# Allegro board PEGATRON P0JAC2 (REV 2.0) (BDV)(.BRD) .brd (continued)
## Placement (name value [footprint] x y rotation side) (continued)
R7160  -  [TX_R0402]  71.4 24.42 0 bottom
R7161  -  [TX_R0402]  69.8 24.63 180 bottom
R7166  -  [TX_R0402]  58.64 13.01 180 bottom
R7171  -  [TX_R0402]  60.42 14.55 0 bottom
R7177  -  [TX_R0402]  65.17 14.66 180 bottom
R7178  -  [TX_R0402]  61.95 12.63 0 bottom
R7181  -  [TX_R0402]  64.62 24.52 180 bottom
R7182  -  [TX_R0402]  64.24 25.71 270 bottom
R7183  -  [R0603]  63.22 24.72 90 bottom
R7184  -  [TX_R0402]  65.18 13.14 0 bottom
R7185  -  [TX_R0402]  61.77 13.88 90 bottom
R7186  -  [TX_R0402]  85.19 14.11 270 bottom
R7189  -  [TX_R0402]  85.95 14.11 270 bottom
R7190  -  [TX_R0402]  61.77 15.43 90 bottom
R7194  -  [TX_R0402]  65.75 23.75 270 bottom
R7195  -  [TX_R0402]  59.97 16.44 270 bottom
R7199  -  [TX_R0402]  66.47 22.15 270 bottom
R7355  -  [TX_R0402]  46.53 12.63 0 bottom
R7356  -  [TX_R0402]  46.53 13.37 0 bottom
R7357  -  [TX_R0402]  48.05 13.37 0 bottom
R7358  -  [TX_R0402]  44.98 13.37 0 bottom
R7359  -  [TX_R0402]  43.28 14.46 180 bottom
R7360  -  [TX_R0402]  48.06 12.63 180 bottom
R7370  -  [TX_R0402]  80.01 9.11 270 bottom
R7371  -  [TX_R0402]  80.75 9.11 270 bottom
R7373  -  [TX_R0402]  82.55 5.83 180 bottom
R7374  -  [TX_R0402]  78.26 9.11 270 bottom
R8100  -  [TX_R0402]  73.94 45.73 180 bottom
R8101  -  [TX_R0402]  73.94 41.54 90 bottom
R8103  -  [TX_R0402]  73.83 44.61 90 bottom
R8111  -  [TX_R0402]  74.68 41.54 270 bottom
R8112  -  [TX_R0402]  73.1 44.61 270 bottom
R8113  -  [TX_R0402]  72.08 41.45 180 bottom
R8114  -  [TX_R0402]  73.2 41.54 90 bottom
R8116  -  [TX_R0603_0OHM_H24]  35.58 40.19 180 bottom
R8117  -  [TX_R0402]  35.36 41.51 90 bottom
R8118  -  [TX_R0402]  43.31 48.35 270 bottom
R8119  -  [TX_R0402]  43.31 49.9 90 bottom
R8120  -  [TX_R0402]  35.43 43.42 0 bottom
R8121  -  [TX_R0402_0OHM]  30.73 42.38 270 bottom
R8122  -  [TX_R0603_0OHM_H24]  36.54 44.54 0 bottom
R8123  -  [TX_R0402]  34.62 41.51 270 bottom
R8124  -  [TX_R0402]  80.04 83.46 0 bottom
R8125  -  [TX_R0402]  74.46 82.29 270 bottom
R8126  -  [TX_R0402]  73.73 82.29 90 bottom
R8127  -  [TX_R0402]  79.63 82.31 270 bottom
R8128  -  [TX_R0402]  73.73 84.67 90 bottom
R8129  -  [TX_R0402]  39.9 47.99 0 bottom
R8130  -  [TX_R0402]  39.9 48.75 0 bottom
R8131  -  [TX_R0402]  40.26 49.92 90 bottom
R8132  -  [TX_R0402]  36.12 41.51 270 bottom
R8133  -  [TX_R0402]  36.96 43.01 0 bottom
R8203  -  [TX_R1206_H30]  67.18 50.25 90 bottom
R8205  -  [TX_R1206_H30]  59.38 51.9 0 bottom
R8208  -  [TX_R0603_H24]  73.78 28.58 180 bottom
R8209  -  [TX_R0402]  71.07 32.14 180 bottom
R8210  -  [TX_R0402]  54.08 52 90 bottom
R8211  -  [TX_R0402]  68.81 52.08 270 bottom
R8212  -  [TX_R0402]  51.43 22.97 180 bottom
R8213  -  [TX_R0603_H24]  46.27 37.3 90 bottom
R8214  -  [TX_R0402]  69.57 52.08 270 bottom
R8216  -  [TX_R0603_H24]  45.41 29.8 270 bottom
R8218  -  [TX_R0603_0OHM_H24]  59.82 22.06 0 bottom
R8224  -  [TX_R0402]  54.91 21.26 90 bottom
R8227  -  [TX_R0603_H24]  50.03 15.07 180 bottom
R8250  -  [TX_R0402]  50.03 19.26 0 bottom
R8301  -  [TX_R0402]  45.97 32.34 270 bottom
R8302  -  [TX_R0402]  72.82 25.54 270 bottom
R8305  -  [TX_R0402]  44.47 43.04 90 bottom
R8306  -  [TX_R0402]  44.82 38.78 180 bottom
R8307  -  [TX_R0402]  44.82 39.51 180 bottom
R8308  -  [TX_R0402]  42.88 45.98 90 bottom
R8309  -  [TX_R0402]  43.63 39.07 90 bottom
R8310  -  [TX_R0603_H24]  56.01 22.72 90 bottom
R8312  -  [TX_R0402]  58.31 18.04 270 bottom
R8313  -  [TX_R0402]  73.91 24.9 270 bottom
R8314  -  [TX_R0402]  75.9 24.47 0 bottom
R8315  -  [TX_R0402]  80.04 27.16 90 bottom
R8316  -  [TX_R0402]  80.41 26.02 0 bottom
R8317  -  [TX_R0402]  35.68 59.9 0 bottom
R8318  -  [TX_R0402]  35.81 65.47 90 bottom
R8320  -  [TX_R0603_H24]  70.74 40.78 90 bottom
R8323  -  [TX_R0402_H22]  87.81 108.52 270 bottom
R8324  -  [TX_R0402_H22]  39.29 2.8 0 bottom
R8325  -  [TX_R0402]  73.74 30.92 270 bottom
R8326  -  [TX_R0402]  76.84 30.95 270 bottom
R8327  -  [TX_R0402_H22]  51.68 59.56 0 bottom
R8328  -  [TX_R0402]  75.31 30.95 270 bottom
R8329  -  [TX_R0402]  76.07 30.95 270 bottom
R8330  -  [TX_R0402]  72.93 34.09 270 bottom
R8335  -  [TX_R0402]  57.56 19.57 270 bottom
R8337  -  [TX_R0402]  45.87 53.12 180 bottom
R8340  -  [TX_R0402]  72.92 32.55 90 bottom
R8365  -  [TX_R0402]  71.75 28.01 180 bottom
R8366  -  [TX_R0201_0OHM_H10]  43.05 40.55 270 bottom
R8367  -  [TX_R0402]  57.56 18.02 90 bottom
R8368  -  [TX_R0402]  56.84 19.57 90 bottom
R8369  -  [TX_R0402]  80.44 22.62 180 bottom
R8370  -  [TX_R0402]  78.87 23.25 0 bottom
R8372  -  [TX_R0402]  75.65 29.78 180 bottom
R8373  -  [TX_R0402_H22]  40.37 28.22 270 bottom
R8375  -  [TX_R0402]  46.3 43.98 90 bottom
R8376  -  [TX_R0402]  47.07 43.98 90 bottom
R8377  -  [TX_R0402]  64.01 21.52 270 bottom
R8379  -  [TX_R0402]  80.09 23.73 270 bottom
R8401  -  [TX_R0201_0OHM_H10]  58.67 20.94 270 bottom
R8404  -  [TX_R0402]  37.87 41.89 90 bottom
R8405  -  [TX_R0402]  42.46 42 90 bottom
R8406  -  [TX_R0402]  39.5 49.92 270 bottom
R8417  -  [TX_R0402]  59.82 19.57 90 bottom
R8430  -  [TX_R0402]  35.68 52.31 90 bottom
R8431  -  [TX_R0402]  69.82 26.63 180 bottom
R8435  -  [TX_R0402]  69.82 25.89 180 bottom
R8437  -  [TX_R0402]  31.09 50.71 270 bottom
R8438  -  [TX_R0402]  36.57 52.16 90 bottom
R8448  -  [TX_R0201_0OHM_H10]  59.21 20.94 90 bottom
R8449  -  [TX_R0402]  73.68 27.24 270 bottom
R8450  -  [TX_R0402]  72.04 35.85 270 bottom
R8456  -  [TX_R0402]  74.85 33.72 0 bottom
R8457  -  [TX_R0402]  72.82 35.86 270 bottom
R8458  -  [TX_R0402]  74.85 34.48 0 bottom
R8501  -  [TX_R0402]  45.13 51.72 0 bottom
R8502  -  [TX_R0402]  46.68 50.99 0 bottom
R8503  -  [TX_R0402]  46.68 50.25 0 bottom
R8504  -  [TX_R0402]  46.68 51.72 0 bottom
R8505  -  [TX_R0402]  45.13 50.99 0 bottom
R8506  -  [TX_R0402]  45.13 50.25 0 bottom
R8507  -  [TX_R0402]  49.35 25.23 0 bottom
R8508  -  [TX_R0402]  49.35 24.49 180 bottom
R8509  -  [TX_R0402]  69.72 27.39 180 bottom
R8510  -  [TX_R0402]  69.72 28.13 0 bottom
R8511  -  [TX_R0402]  69.55 32.14 0 bottom
R8515  -  [TX_R0402]  47.07 45.55 90 bottom
R8517  -  [TX_R0402]  46.3 45.55 270 bottom
R8526  -  [TX_R0402]  45.03 47.94 0 bottom
R8527  -  [TX_R0402]  45.03 49.41 0 bottom
R8528  -  [TX_R0201_H10]  71.43 37.98 180 bottom
R8529  -  [TX_R0201_H10]  71.43 37.46 180 bottom
R8530  -  [TX_R0402]  45.03 48.68 0 bottom
R8531  -  [TX_R0201_0OHM_H10]  71.43 36.89 180 bottom
R8800  -  [TX_R0603_H24]  37.74 24.16 0 bottom
R8801  -  [TX_R0805_H26]  67.11 8.47 270 bottom
R8803  -  [TX_R0402]  34.39 18.04 90 bottom
R8804  -  [TX_R0402]  29.2 26.6 90 bottom
R8805  -  [TX_R0402]  34.64 20.38 270 bottom
R8806  -  [TX_R0402]  30.7 20.37 270 bottom
R8807  -  [TX_R0402_0OHM]  30.51 24.7 180 bottom
R8808  -  [TX_R0402_0OHM]  29.58 23.07 0 bottom
R8809  -  [TX_R0402]  29.58 22.34 180 bottom
R8810  -  [TX_R0402]  30.7 23.43 270 bottom
R8811  -  [TX_R0402]  33.73 20.41 270 bottom
R8812  -  [TX_R0402]  39.24 26.22 0 bottom
R8813  -  [TX_R0402_H22]  39.24 26.96 0 bottom
R8814  -  [TX_R0402]  39.31 24.98 90 bottom
R8820  -  [TX_R0402]  32.43 15.66 90 bottom
R8821  -  [TX_R0402]  33.43 16.93 0 bottom
R8822  -  [TX_R0402]  29.2 25.05 90 bottom
R8825  -  [TX_R0402]  29.85 18.7 90 bottom
R8826  -  [TX_R0402]  31.45 18.35 270 bottom
R8833  -  [TX_R0402_0OHM]  31.43 20.39 90 bottom
R8834  -  [TX_R0402]  29.97 20.49 90 bottom
R8835  -  [TX_R0402]  29.58 23.83 0 bottom
R8874  -  [TX_R0402]  32.18 20.39 90 bottom
R8875  -  [TX_R0402]  32.89 18.35 90 bottom
R8876  -  [TX_R0402]  32.18 18.35 90 bottom
R8878  -  [TX_R0402]  32.89 20.38 90 bottom
R8903  -  [TX_R0402]  30.02 33.94 180 bottom
R8904  -  [TX_R0402]  30.03 36.18 0 bottom
R8905  -  [TX_R0402]  32.15 37.7 90 bottom
R8906  -  [TX_R0402]  34.82 38.19 0 bottom
R8907  -  [TX_R0402]  34.44 33.93 90 bottom
R8908  -  [TX_R0805_H24]  29.21 48.07 90 bottom
R8910  -  [TX_R0402]  29.24 46.16 180 bottom
R8923  -  [TX_R0402]  29.93 37.7 270 bottom
R8944  -  [TX_R0402]  30.02 34.68 0 bottom
R8971  -  [TX_R0402]  29.2 37.7 270 bottom
R8972  -  [TX_R0402]  30.66 37.7 270 bottom
R8973  -  [TX_R0402]  31.41 37.7 270 bottom
R8974  -  [TX_R0402]  29.31 44.76 180 bottom
R9000  -  [TX_R0402]  41.17 22.26 180 bottom
R9001  -  [TX_R0402]  47.11 22.31 180 bottom
R9002  -  [TX_R0402]  47.11 23.05 0 bottom
R9003  -  [TX_R0402]  41.17 26.68 180 bottom
R9004  -  [TX_R0402_0OHM]  41.17 21.52 0 bottom
R9005  -  [TX_R0402]  41.17 23 0 bottom
R9006  -  [TX_R0805_H26]  47.14 20.53 270 bottom
RN0900  -  [TX_2R4P0402_H18]  87.92 44.46 90 bottom
RN0901  -  [TX_2R4P0402_H18]  87.92 47.51 90 bottom
RN0902  -  [TX_2R4P0402_H18]  87.92 41.31 90 bottom
RN0903  -  [TX_2R4P0402_H18]  87.92 38.21 90 bottom
RN2104  -  [TX_2R4P0402_H18]  21.36 98.36 180 bottom
RN2105  -  [TX_2R4P0402_H18]  22.57 98.36 180 bottom
RN7309  -  [TX_2R4P0402_H18]  64.56 6.56 270 bottom
RN7337  -  [TX_2R4P0402_H18]  64.56 7.96 270 bottom
RN7338  -  [TX_2R4P0402_H18]  64.56 5.22 270 bottom
RN7340  -  [TX_2R4P0402_H18]  64.59 2.45 270 bottom
RN7341  -  [TX_2R4P0402_H18]  64.56 3.82 270 bottom
RNX5227  -  [TX_2R4P0402_H18]  87.88 58.25 90 bottom
SP2601  -  [NB_R0402_SHORT_5MIL_SMALL]  64.11 61.8 90 bottom
SP2602  -  [NB_R0402_SHORT_5MIL_SMALL]  43.42 59.57 0 bottom
SP2603  -  [NB_R0402_SHORT_5MIL_SMALL]  38.38 100.97 270 bottom
SP7301  -  [HH_R0402_SHORT_12MIL]  82.25 9.06 0 bottom
SP7302  -  [HH_R0402_SHORT_12MIL]  77.06 6.84 180 bottom
SP7303  -  [HH_R0402_SHORT_12MIL]  79.12 5.04 180 bottom
SP7304  -  [HH_R0402_SHORT_12MIL]  77.06 6 0 bottom
SP7305  -  [HH_R0402_SHORT_12MIL]  79.15 4.2 0 bottom
SP7306  -  [HH_R0402_SHORT_12MIL]  81.1 4.76 180 bottom
SP7307  -  [HH_R0402_SHORT_12MIL]  86.03 8.98 180 bottom
SP7308  -  [HH_R0402_SHORT_12MIL]  86.72 5.04 0 bottom
SR8100  -  [NB_PWR_FB_SHORT_PT]  34.92 44.99 90 bottom
SR8501  -  [NB_R0402_SHORT_5MIL_SMALL]  55.96 20.66 270 bottom
SR8900  -  [NB_R0402_SHORT]  36.42 37.93 90 bottom
SR9000  -  [NB_R0402_SHORT]  47.36 24.98 0 bottom
SR9001  -  [NB_R0402_SHORT]  47.36 23.94 0 bottom
SR9002  -  [NB_R0402_SHORT]  47.36 26.02 0 bottom
SR9003  -  [NB_R0402_SHORT]  43.96 27.95 90 bottom
SW2004  -  [TX_SW_3P_45_2HOLD]  100.5 95.6 270 bottom
T1101  -  [NB_TPC26T_68]  10.09 65.99 180 bottom
T1102  -  [NB_TPC26T_68]  16.16 66.14 180 bottom
T1103  -  [NB_TPC26T_68]  32.11 65.3 180 bottom
T1104  -  [NB_TPC26T_68]  34.57 7.03 180 bottom
T1105  -  [NB_TPC26T_68]  30.23 61.74 180 bottom
T1106  -  [NB_TPC26T_68]  31.4 63.09 180 bottom
T1610  -  [NB_TPC26T_68]  69.55 81.16 180 bottom
T1611  -  [NB_TPC26T_68]  85.14 45.98 180 bottom
T1901  -  [NB_TPC22T_68]  31.79 69.1 0 bottom
T1902  -  [NB_TPC22T_68]  27.97 75.47 0 bottom
T1903  -  [NB_TPC22T_68]  32.51 71.89 270 bottom
T1904  -  [NB_TPC22T_68]  21.84 86.57 0 top
T1905  -  [NB_TPC22T_68]  21.74 92.44 0 top
T2005  -  [NB_TPC26T_68]  94.49 93.53 180 bottom
T2006  -  [NB_TPC26T_68]  88.27 39.63 180 bottom
T2007  -  [NB_TPC26T_68]  13.7 66.01 180 bottom
T2008  -  [NB_TPC26T_68]  11.88 65.96 180 bottom
T2009  -  [NB_TPC26T_68]  8.97 75.98 180 bottom
T2010  -  [NB_TPC26T_68]  40.92 7.16 180 bottom
T2011  -  [NB_TPC26T_68]  8.35 66.12 180 bottom
T2012  -  [NB_TPC26T_68]  8.38 63.46 180 bottom
T2013  -  [NB_TPC26T_68]  88.19 45.96 180 bottom
T2101  -  [NB_TPC22T_68]  11.14 120.61 180 bottom
T2102  -  [NB_TPC22T_68]  1.96 120.33 180 bottom
T2103  -  [NB_TPC22T_68]  12.07 122.08 180 bottom
T2104  -  [NB_TPC22T_68]  1.96 122.06 180 bottom
T2301  -  [NB_TPC26T_68]  79.48 3.25 180 bottom
T2302  -  [NB_TPC26T_68]  29.71 78.56 180 bottom
T2508  -  [NB_TPC22T_68]  59.11 71.46 0 top
T2509  -  [NB_TPC22T_68]  62.38 70.9 0 top
T2541  -  [NB_TPC22T_68]  58.04 72.91 0 top
T2542  -  [NB_TPC22T_68]  72.9 74.46 180 bottom
T2600  -  [NB_TPC22T_68]  39.42 63.89 270 bottom
T2601  -  [NB_TPC22T_68]  40.3 62.39 270 bottom
T2602  -  [NB_TPC22T_68]  38.47 62.39 270 bottom
T2608  -  [NB_TPC22T_68]  61.7 67.5 270 top
T2618  -  [NB_TPC22T_68]  61.62 65.72 0 top
T2623  -  [NB_TPC22T_68]  47.63 62.9 0 top
T2624  -  [NB_TPC22T_68]  88.77 90.56 180 bottom
T2625  -  [NB_TPC22T_68]  84.91 70.63 180 bottom
T2646  -  [NB_TPC22T_68]  45.52 68.41 0 top
T2657  -  [NB_TPC22T_68]  48.05 73.03 0 top
T2670  -  [NB_TPC22T_68]  63.25 68.31 0 top
T2685  -  [NB_TPC22T_68]  61.24 69.28 0 top
T2686  -  [NB_TPC22T_68]  40.18 65.44 180 bottom
T2700  -  [NB_TPC22T_68]  56.26 74.41 270 top
T2701  -  [NB_TPC22T_68]  50.8 74.41 0 top
T2702  -  [NB_TPC22T_68]  53.06 73.47 0 top
T2703  -  [NB_TPC22T_68]  55.63 66.33 270 top
T2704  -  [NB_TPC22T_68]  54.79 73.34 0 top
T2705  -  [NB_TPC22T_68]  61.42 72.6 0 top
T2706  -  [NB_TPC26T_68]  79.29 67.26 180 bottom
T2707  -  [NB_TPC26T_68]  90.63 93.86 180 bottom
T3002  -  [NB_TPC26T_68]  71.18 70.1 270 top
T3003  -  [NB_TPC26T_68]  70.04 71.67 270 top
T3005  -  [NB_TPC26T_68]  25.05 98.56 180 bottom
T3006  -  [NB_TPC26T_68]  25.5 100.26 180 bottom
T3007  -  [NB_TPC26T_68]  84.99 84.9 180 bottom
T3008  -  [NB_TPC26T_68]  21.97 106.77 180 bottom
T3010  -  [NB_TPC22T_68]  68.45 68.44 0 top
T3101  -  [NB_TPC22T_68]  53.29 107.58 180 bottom
T3801  -  [NB_TPC22T_68]  87.58 103.46 180 bottom
T3802  -  [NB_TPC22T_68]  87.43 101.43 180 bottom
T3803  -  [NB_TPC22T_68]  89.18 85.3 180 bottom
T3804  -  [NB_TPC22T_68]  88.88 87.03 180 bottom
T5401  -  [NB_TPC22T_68]  16.4 76.59 180 bottom
T5402  -  [NB_TPC22T_68]  10.44 69.6 180 bottom
T5403  -  [NB_TPC22T_68]  20.96 77.05 0 top
T5404  -  [NB_TPC22T_68]  14.22 69.6 180 bottom
T5405  -  [NB_TPC22T_68]  6.06 71.28 180 bottom
T5406  -  [NB_TPC22T_68]  84.96 103.92 180 bottom
T5407  -  [NB_TPC22T_68]  6.53 72.95 180 bottom
T5807  -  [NB_TPC22T_68]  27.38 99.81 180 bottom
T8001  -  [NB_TPC26T_68]  73.23 7.78 0 bottom
T8002  -  [NB_TPC26T_68]  71.44 7.72 0 bottom
T8004  -  [NB_TPC26T_68]  87.12 26.1 0 bottom
T8005  -  [NB_TPC26T_68]  85.28 11.13 0 bottom
T8006  -  [NB_TPC26T_68]  75.7 7.78 0 bottom
T8100  -  [NB_TPC28T_68]  75.74 44.99 270 top
T8101  -  [NB_TPC22T_68]  34.8 39.1 180 bottom
T8102  -  [NB_TPC22T_68]  34.34 44.15 0 top
T8103  -  [NB_TPC22T_68]  32.6 44.09 0 top
T8104  -  [NB_TPC22T_68]  38.13 44.24 180 bottom
T8105  -  [NB_TPC22T_68]  74.02 86.01 180 bottom
T8106  -  [NB_TPC22T_68]  85.04 80.91 180 bottom
T8107  -  [NB_TPC22T_68]  34.44 109.69 180 bottom
T8201  -  [NB_TPC22T_68]  37 33.48 180 bottom
T8202  -  [NB_TPC22T_68]  75.43 28.65 180 bottom
T8203  -  [NB_TPC22T_68]  78.61 30.06 180 bottom
T8204  -  [NB_TPC22T_68]  48.4 22.44 180 bottom
T8205  -  [NB_TPC22T_68]  41.54 13.91 180 bottom
T8206  -  [NB_TPC22T_68]  46.13 38.88 180 bottom
T8207  -  [NB_TPC22T_68]  69.69 106.08 180 bottom
T8304  -  [NB_TPC26T_68]  58.62 17.26 270 top
T8305  -  [NB_TPC22T_68]  43.33 32.44 180 bottom
T8306  -  [NB_TPC22T_68]  42.09 43.72 270 bottom
T8307  -  [NB_TPC22T_68]  14.68 106.33 270 bottom
T8308  -  [NB_TPC22T_68]  22.86 71.4 270 bottom
T8309  -  [NB_TPC22T_68]  41.82 46.09 270 bottom
T8310  -  [NB_TPC22T_68]  42.7 39.46 270 bottom
T8311  -  [NB_TPC22T_68]  93.92 85.79 270 bottom
T8312  -  [NB_TPC22T_68]  27.97 78.69 270 bottom
T8313  -  [NB_TPC22T_68]  86.52 36.95 270 bottom
T8314  -  [NB_TPC22T_68]  26.19 78.62 180 bottom
T8315  -  [NB_TPC22T_68]  38.94 106.46 180 bottom
T8316  -  [NB_TPC22T_68]  61.74 106.06 180 bottom
T8317  -  [NB_TPC22T_68]  45.73 106.35 180 bottom
T8318  -  [NB_TPC26T_68]  36.96 35.76 180 bottom
T8319  -  [NB_TPC26T_68]  49.18 110.3 180 bottom
T8320  -  [NB_TPC22T_68]  41.07 32.99 270 bottom
T8321  -  [NB_TPC22T_68]  55.38 29.09 270 top
T8322  -  [NB_TPC22T_68]  45.42 42.99 180 bottom
T8323  -  [NB_TPC22T_68]  48.11 42.2 180 bottom
T8403  -  [NB_TPC22T_68]  55.96 41.16 270 top
T8405  -  [NB_TPC22T_68]  53.49 38.39 270 top
T8406  -  [NB_TPC22T_68]  51.87 39.53 270 top
T8407  -  [NB_TPC22T_68]  54.36 40.4 270 top
T8410  -  [NB_TPC22T_68]  54.03 36.43 270 top
T8411  -  [NB_TPC22T_68]  52.71 35.26 270 top
T8415  -  [NB_TPC22T_68]  60.56 20.86 270 bottom
T8416  -  [NB_TPC22T_68]  57.86 30.9 270 top
T8417  -  [NB_TPC22T_68]  62.71 7.71 180 bottom
T8418  -  [NB_TPC22T_68]  77.17 108.54 180 bottom
T8419  -  [NB_TPC22T_68]  38.28 46.34 180 bottom
T8420  -  [NB_TPC22T_68]  86.84 84.08 180 bottom
T8425  -  [NB_TPC22T_68]  55.96 25.74 270 top
T8426  -  [NB_TPC22T_68]  58.85 29.47 0 top
T8428  -  [NB_TPC22T_68]  59.97 39.18 0 top
T8430  -  [NB_TPC22T_68]  63.35 41.06 180 bottom
T8431  -  [NB_TPC22T_68]  62.64 35.72 0 top
T8464  -  [NB_TPC22T_68]  52.76 41.06 0 top
T8501  -  [NB_TPC22T_68]  70.31 38.72 90 top
T8502  -  [NB_TPC22T_68]  70.77 37.02 90 top
T8503  -  [NB_TPC22T_68]  46.41 47.58 90 bottom
T8504  -  [NB_TPC22T_68]  46.36 49.35 90 bottom
T8505  -  [NB_TPC22T_68]  43.79 47.05 90 bottom
T8506  -  [NB_TPC22T_68]  79.27 61.63 180 bottom
T8507  -  [NB_TPC22T_68]  77.39 61.48 180 bottom
T8800  -  [NB_TPC22T_68]  37.31 16.67 0 bottom
T8801  -  [NB_TPC26T_68]  66.23 6.47 180 bottom
T8802  -  [NB_TPC26T_68]  85.37 39.74 180 bottom
T8902  -  [NB_TPC28T_68]  33.36 35.65 0 top
T8903  -  [NB_TPC28T_68]  30.02 34.93 0 top
T8904  -  [NB_TPC28T_68]  32.84 32.6 180 bottom
T8905  -  [NB_TPC28T_68]  8.5 68.11 180 bottom
T8906  -  [NB_TPC28T_68]  29.85 37.27 0 top
T8907  -  [NB_TPC28T_68]  31.6 37.22 0 top
U1001  -  [TX_QFN_48P_16_S236_P_RE_10V]  27.55 65.74 180 bottom
U1101  -  [TX_MICROPHONE_6P_148X186_KN]  98.14 111.96 270 top
U1601  -  [TX_BGA_253P_20_492X492]  65.36 93.98 270 bottom
U1701  -  [TX_BGA_253P_20_492X492]  47.58 93.98 270 bottom
U1915  -  [TX_BGA_169P_20_630X472_H39]  30.98 90.48 180 bottom
U2101  -  [TX_SOT23_S5_H57]  77.86 96.99 180 bottom
U2301  -  [TX_SOT23_S5_H57]  86.31 2.8 0 bottom
U2400  -  [T_HH_BGA_1380P_669X669]  53.42 71.02 270 bottom
U3001  -  [TX_QFP_64P_16_354X354_H63]  72.76 68.54 0 bottom
U3301  -  [TX_BGA_24P_20_118X118]  77.04 87.74 270 bottom
U3302  -  [TX_DFN_8P_50_197X236_PAD_WI]  76.71 92.69 90 bottom
U3304  -  [TX_DFN_8P_18_79X79]  78.46 78.57 180 bottom
U5101  -  [TX_QFN_10P_20_79X61]  29.29 8.32 270 bottom
U5203  -  [TX_SOIC_8P_26_122X193]  73.76 51.44 90 bottom
U5401  -  [TX_LGA_96P_20_12PAD_FOXCO]  9.6 85.04 270 bottom
U5801  -  [TX_QFN_24P_16_S118_P_INVH37]  31.78 99.37 180 bottom
U5803  -  [TX_OPLGA_6P_24_71X93_CAPELL]  92.96 117.46 90 top
U5804  -  [TX_BGA_8P_16_47X47]  68.22 117.16 180 bottom
U5806  -  [TX_SOT23_2D4_H57]  94.7 79.9 0 top
U7107  -  [TX_QFN_48P_20_S276_P_QL_16V]  69.72 17.61 0 bottom
U7112  -  [TX_SO8_H69]  13.67 61.66 270 bottom
U7141  -  [TX_SOT23_S5_H57]  54.25 17.18 0 bottom
U7311  -  [TX_SOT23_S5_H57]  46.16 15.39 0 bottom
U7320  -  [TX_BGA_6P_20_55X35]  82.63 7.4 180 bottom
U7321  -  [TX_BGA_8P_20_75X35]  79.5 7.35 180 bottom
U7322  -  [TX_BGA_6P_20_55X35]  86.49 7.35 180 bottom
U7903  -  [NB_SHIELDING_52P_2HOLD]  54.71 32.85 0 bottom
U7911  -  [SMD79X157_NP]  17.76 9.9 180 bottom
U7913  -  [SMD79X157_NP]  45.73 1.01 270 bottom
U7920  -  [SMDPAD_394X394_NP]  34.92 6.31 0 top
U7921  -  [SMDPAD_394X394_NP]  14.1 100.24 0 top
U7922  -  [SMDPAD_394X394_NP]  28.06 55.08 0 top
U7931  -  [SMDPAD79X315_NP]  17.75 9.9 0 top
U7932  -  [SMDPAD79X315_NP]  45.7 1 90 top
U7942  -  [NB_SHIELD_58P_2H_2508X1831]  58.44 86.54 0 bottom
U8100  -  [TX_QFN_16P_26_S157_PD_TI_4V]  77.52 43.04 270 bottom
U8101  -  [TX_BGA_12P_16_66X51]  32.56 43.01 0 bottom
U8102  -  [TX_SOT23_S5_H57]  77.06 83.25 0 bottom
U8201  -  [TX_BGA_224P_16_244X244]  58.72 34.94 0 bottom
U8800  -  [TX_QFN_24P_20_S157_P_QU_4V]  33.97 23.43 180 bottom
U8901  -  [T_CSP_15P_20_103X77]  32.39 34.58 270 bottom
U9000  -  [TX_QFN_16P_20_S118_P_KT_5V]  44.22 24.42 90 bottom
X2600  -  [TX_XTAL_4P_126X98_EPSON]  39.98 60.39 180 bottom
X2601  -  [TX_XTAL_2P_126X59]  65.37 60 180 bottom

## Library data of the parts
C0706 C0710 C0715 C1902 C1905 C1909 C2011 C2608 C2611 C2612 C3317-C3319 C3801 C5402 C5405 C5878 C7104 C7105 = DEV_12
C0707 C0708 C0713 C0901 C1022 C1024 C1025 C1052 C1105 C1601-C1609 C1614 C1616 C1618 C1619 C1622 C1625 C1701 C1703 C1705 C1707 C1709-C1717 C1722 C1725 C1900 C1903 C1904 C1912-C1916 C2102 C2104 C2124 C2125 C2602 C2603 C2706 C2707 C2709 C2710 C2713 C2717 C2722-C2724 C2728-C2730 C2733 C2735-C2737 C2747 C2748 C2752-C2754 C2758-C2763 C2766-C2768 C2771 C2774 C2776 C2777 C2800 C2802-C2804 C2806-C2811 C2814 C2815 C2817-C2825 C3001 C5102 C5103 C5412 C5414 C5415 C7001 C7002 C7010 C7106 C7110 C7117 C7118 C7120 C7351 C7355-C7357 C7359 C8402 = DEV_10
C0714 C0787 C0951 C0952 C1911 C2122 C2600 C2601 C5217 C5403 C5413 C5416 C5841 C5866 C5867 C7166 C7187 C7341 C7342 C7350 C7353 C7364 C8299 C8367 = DEV_9
C0722 = DEV_28
C0902 C0903 C0904 C0905 C0906 C0907 C0908 C0909 C0910 C1002 C1020 C1021 C1023 C1026 C1027 C1029 C1053 C1615 C1617 C1623 C1624 C1702 C1704 C1723 C1724 C2036 C2101 C2126 C2401 C2604 C2732 C2772 C2773 C3101 C3311 C3316 C5101 C5209 C5215 C5216 C5404 C5407 C5410 C5411 C5417 C5810-C5813 C5819 C5820 C7003 C7011 C7146-C7149 C7352 C7354 C7377 C8003-C8005 = DEV_29
C1001 C1007 C1008 C1028 C1030 C1040 C1106 C7385 = DEV_65
C1003-C1006 C2718 C2727 C7119 C7317 C7318 C7358 = DEV_24
C1010 C1044-C1047 C1060-C1063 C2605 C7312 C7313 = DEV_27
C1102 = DEV_25
C2127 C2128 C8107 = DEV_157: room: 5V
C2301 = DEV_151
C2606 = DEV_164
C2610 = DEV_156
C2701 C7316 = DEV_58
C2734 C2816 C5211 C5212 C5401 C5406 C7103 = DEV_11
C3002 = DEV_68
C3003-C3011 = DEV_155
C5210 C5214 = DEV_154
C7108 C7109 C7111 C7112 C7330 C7331 C7388-C7391 = DEV_153
C7125 = DEV_193
C7126 C8111 C8112 = DEV_13: room: +3V_EC
C7150 = DEV_52
C7321-C7324 = DEV_23
C8001 = DEV_59
C8002 = DEV_152
C8100 = DEV_26: room: 5V
C8101 C8105 C8108 = DEV_13: room: 5V
C8102 C8106 = DEV_29: room: 5V
C8109 = DEV_58: room: +3V_EC
C8110 C8113 = DEV_151: room: +3V_EC
C8114 = DEV_29: room: +3V_EC
C8115 C8116 C8290 C8291 C8309 C8314 C8317 C8329 C8330 C8332-C8336 C8348 C8349 C8405-C8408 = DEV_10: room: PMIC
C8201-C8210 C8229 C8235 C8239 C8246 C8251 C8258 C8307 C8327 = DEV_65: room: PMIC
C8211-C8218 C8220-C8227 C8230-C8233 C8237 C8241 C8242 C8244 C8245 C8248-C8250 C8253-C8257 C8273-C8289 C8302 C8303 C8320-C8326 = DEV_13: room: PMIC
C8219 C8228 = DEV_150: room: PMIC
C8260-C8265 C8304 C8305 C8311-C8313 C8318 = DEV_58: room: PMIC
C8266-C8271 C8308 C8412 = DEV_29: room: PMIC
C8301 C8306 C8410 C8411 = DEV_156: room: PMIC
C8310 C8316 C8342 C8401 C8409 = DEV_149: room: PMIC
C8315 C8331 = DEV_11: room: PMIC
C8319 = DEV_24: room: PMIC
C8341 C8343 C8345 = DEV_25: room: PMIC
C8344 C8346 = DEV_148: room: PMIC
C8800 = DEV_147: room: CHG
C8801 C8804 C8805 = DEV_64: room: CHG
C8802 = DEV_146: room: CHG
C8803 C8808 C8811 C8816-C8818 = DEV_29: room: CHG
C8806 C8807 = DEV_9: room: CHG
C8809 C8810 = DEV_13: room: CHG
C8812 = DEV_58: room: CHG
C8814 = DEV_145: room: CHG
C8905-C8907 C8911 C8913 C8917-C8919 = DEV_29: room: GASG
C8912 = DEV_69: room: GASG
C8916 = DEV_10: room: GASG
C9000 = DEV_29: room: BL
C9001 C9004 = DEV_24: room: BL
C9002 C9007 = DEV_10: room: BL
C9003 = DEV_52: room: BL
C9005 C9010 = DEV_144: room: BL
C9006 = DEV_143: room: BL
C9008 = DEV_142: room: BL
C9009 = DEV_141: room: BL
CE5201 CE5202 = DEV_51
CE8100 CE8101 = DEV_51: room: 5V
CE8102 = DEV_140: room: +3V_EC
CON0700 = DEV_139
CON0901 = DEV_138
CON1102 = DEV_163
CON2002 = DEV_136
CON2003 = DEV_135
CON2101 = DEV_162
CON3301 = DEV_134
CON3800 = DEV_57
CON5101 = DEV_161
CON5201 = DEV_133
CON7305 = DEV_170
CON8001 = DEV_137
CON8902 = DEV_187
D0700 D0701 D0702 D0703 D0704 D0705 D0706 D1101-D1104 = DEV_132
D0905 D5102 D5104 = DEV_50
D2003 D5103 = DEV_131
D2701 D8101 = DEV_49
D8201 = DEV_130: room: PMIC
D9000 D9001 = DEV_129: room: BL
F0921 = DEV_128
H7901 = DEV_127
H7903 H7906 = DEV_126
H7907 = DEV_125
H7910 = DEV_179
H7911 = DEV_178
J3101 = DEV_124
JP1601 = DEV_8: room: 1.05VS
JP1602 JP8101 JP8102 JP9000 = DEV_2: room: BL
JP8100 = DEV_1: room: 5V
JP8201-JP8207 JP8301-JP8305 JP8402 JP8900 JP8901 = DEV_1: room: PMIC
JP8306 JP8307 = DEV_166: room: 1.05VS
JP8800 = DEV_8: room: CHG
JP9001 = DEV_123: room: BL
L0900 L0901 L0902 L0903 L2102 L2104 L5201 LX7324-LX7328 = DEV_48
L3001-L3003 L7303-L7306 L7350 = DEV_66
L5202 L8001 = DEV_122
L7102 = DEV_121
L7111 = DEV_67
L8100 = DEV_120: room: 5V
L8101 = DEV_184
L8201 L8203-L8206 L8208-L8211 L8213 L8215 L8301 = DEV_183: room: PMIC
L8202 L8207 L8212 L8214 L8216 = DEV_184: room: PMIC
L8801 = DEV_119: room: CHG
L9000 = DEV_118: room: BL
Q0703 Q7001 Q7111 = DEV_22
Q0704 Q0901 Q2001 Q2644 Q2650 Q2660 Q3004 Q3006 Q3008 Q3009 Q3101 Q5401 Q7003 Q7142 Q7187 Q7198 Q7199 = DEV_63
Q0902 Q0903 Q2025 Q2655 Q3007 Q3301 = DEV_7
Q7104 = DEV_117
Q8100-Q8102 = DEV_63: room: 5V
Q8202 Q8303 Q8402 Q8405 Q9000 = DEV_22: room: PMIC
Q8203 Q8406 Q8805 = DEV_63: room: PMIC
Q8301 Q8302 = DEV_53: room: PMIC
Q8804 = DEV_116: room: CHG
Q8900 = DEV_117: room: GASG
R0501 R0502 R0503 R0504 R0505 R0507 R0508 R0509 R0510 R0511 R0512 R0513 R0515 R8417 R8449 R8450 R8457 R8458 R8517 = DEV_4: room: PMIC
R0506 R0514 R8528 R8529 = DEV_115: room: PMIC
R0700 R0703 R0755 R0911 R1126 R1612 R1613 R1701 R1702 R2088 R2099 R2402 R2403 R3001 R3015 R3042 R3045 R3060-R3062 R3066 R3077 R3081-R3084 R3343 R3352 R5415 R5418 R5421 R5871 R7006 R7129 R7132 R7139 R7142 R7143 R7154 R7181 R7184 R7185 R7194 R7195 R7199 R7357 = DEV_3
R0704 R0706 R0734 R0737 R0753 R1006-R1010 R1014 R1017 R1020 R1034-R1036 R1038 R1045-R1048 R1050-R1053 R1112 R1113 R1117 R1118 R1120 R1121 R1125 R1127 R1630 R1730 R1901 R1902 R1908 R2008-R2011 R2020 R2030 R2031 R2101 R2103 R2104 R2121 R2123 R2132 R2134 R2137 R2138 R2516-R2518 R2542 R2637 R2685 R2691 R2701 R2710 R2714-R2716 R2720 R2721 R2723 R3046 R3047 R3056 R3080 R3341 R3344 R3348 R3351 R5101 R5201 R5205 R5401-R5414 R5416 R5417 R5420 R5422-R5425 R5427 R5428 R5818-R5821 R5825 R5826 R5833 R5849 R5860 R5861 R5899 R7001 R7002 R7005 R7007 R7102 R7103 R7122 R7135-R7138 R7144 R7145 R7147 R7151-R7153 R7156 R7158 R7160 R7161 R7171 R7177 R7178 R7190 R7355 R7356 R7359 R7360 R8874-R8876 R8878 R8923 R8971-R8973 = DEV_6
R0724 R0757 R0908 R1610 R1611 R1703 R1704 R2021 R2096 R2102 R2130 R2179 R2407 R2408 R2515 R2521 R2522 R2645 R2649 R2658 R2677 R3338-R3340 R5106 R5107 R5110 R5426 R5822 R5824 R5842 R5847 R5848 R5870 R7004 R7106 R7108 R7109 R7113 R7114 R7119 R7127 R7166 R7186 R7189 R7370 R7371 R7373 R8126 R8431 R8435 = DEV_4
R0900 R0901 R0902 R0903 R0904 R0905 R0906 R0907 = DEV_47
R0909 R0910 R0912 R0913 R1026 R1027 R1116 R2667 R2668 R5866 R5867 R7107 R7110 R7115 R7116 = DEV_21
R0914 R2015-R2018 R2040 R2064 R2097 = DEV_114
R1015 R1119 R2612 R2613 R2702 = DEV_20
R1037 R1625 = DEV_56
R1101 R8125 = DEV_15
R1124 R2400 R2401 R2540 R2550 R2650 R2651 R2683 R3036 R3037 R3078 R3079 R3101 R5105 = DEV_45
R1601 R1614 R1724 R1725 = DEV_177
R1602-R1605 R1709-R1712 = DEV_18
R1615-R1624 R1713-R1722 = DEV_19: room: GPU_MEM
R2098 R5204 R5831 = DEV_4: room: FAN
R2129 = DEV_62
R2131 R2600 R7182 = DEV_44
R2301 = DEV_188
R2404 = DEV_43
R2405 = DEV_42
R2406 = DEV_41
R2409-R2411 = DEV_40
R2506 R2507 R2509 R2614 R2622 R2623 = DEV_17
R2508 = DEV_39
R2510 R2511 R7141 R7358 = DEV_38
R2512 = DEV_112
R2601 R2640 R2688 R2692 = DEV_115
R2603 R2608 = DEV_37
R2604 R2638 R2690 R3342 R3350 = DEV_111
R2615 R2641 R2642 = DEV_110
R2617 = DEV_36
R2626 R2627 = DEV_15: room: DIM
R2629 R2630 R2634-R2636 R2676 = DEV_35
R2631 = DEV_34
R2632 = DEV_33
R2633 = DEV_55
R2643 R3315 R3345-R3347 R3810 R8366 = DEV_113
R2659 = DEV_109
R2678 R2687 = DEV_108
R2703 R7374 = DEV_5
R2722 R2724 = DEV_102
R2801 R8800 = DEV_56: room: CHG
R3002 = DEV_46
R3070 = DEV_194
R3803 = DEV_70
R5429-R5433 R8811 = DEV_107
R7104 R7105 = DEV_106
R7183 = DEV_189
R8100 = DEV_105: room: 5V
R8101 R8112-R8114 = DEV_44: room: 5V
R8103 = DEV_104: room: 5V
R8111 = DEV_103: room: 5V
R8116 R8122 = DEV_102: room: +3V_EC
R8117 R8119 R8123 R8124 R8127 R8128 R8132 R8133 R8209 R8212 R8224 R8301 R8302 R8305-R8309 R8312 R8313 R8316 R8318 R8335 R8337 R8340 R8365 R8375-R8377 R8379 R8404 R8430 R8456 R8502 R8503 R8507-R8511 R8515 = DEV_6: room: PMIC
R8118 R8130 = DEV_3: room: 5V
R8120 = DEV_44: room: +3V_EC
R8121 = DEV_114: room: +3V_EC
R8129 R8131 R8803-R8806 R8812 R8814 R8822 R8825 R8826 R8834 R8835 = DEV_4: room: CHG
R8203 R8205 = DEV_101: room: PMIC
R8208 R8213 R8216 R8227 R8310 R8320 = DEV_56: room: PMIC
R8210 R8211 R8214 = DEV_159: room: PMIC
R8218 = DEV_102: room: PMIC
R8250 R8314 R8315 R8317 R8405 R8437 = DEV_3: room: PMIC
R8323 R8324 R8327 R8373 = DEV_32: room: PMIC
R8325 R8326 R8328 R8329 R8372 = DEV_14: room: PMIC
R8330 = DEV_194: room: PMIC
R8367 R8370 = DEV_191: room: PMIC
R8368 = DEV_176: room: PMIC
R8369 = DEV_195: room: PMIC
R8401 R8448 R8531 = DEV_113: room: PMIC
R8406 = DEV_44: room: PMIC
R8438 = DEV_20: room: PMIC
R8501 R8505 R8526 R8527 R8530 = DEV_39: room: PMIC
R8504 = DEV_16: room: PMIC
R8506 = DEV_19: room: PMIC
R8801 = DEV_100: room: CHG
R8807 R8808 R8833 = DEV_114: room: CHG
R8809 R8820 = DEV_3: room: CHG
R8810 = DEV_99: room: CHG
R8813 = DEV_32: room: CHG
R8821 = DEV_20: room: CHG
R8903 = DEV_98: room: GASG
R8904 R8907 = DEV_20: room: GASG
R8905 R8906 = DEV_19: room: GASG
R8908 = DEV_97: room: GASG
R8910 R8974 = DEV_6: room: GASG
R8944 = DEV_104: room: GASG
R9000 = DEV_96: room: BL
R9001 = DEV_44: room: BL
R9002 = DEV_95: room: BL
R9003 = DEV_94: room: BL
R9004 = DEV_114: room: BL
R9005 = DEV_190: room: BL
R9006 = DEV_100: room: BL
RN0900 RN0901 RN0902 RN0903 RN2104 RN2105 RN7309 RN7337 RN7338 RN7340 RN7341 RNX5227 = DEV_31
SP2601-SP2603 = DEV_93
SP7301-SP7308 = DEV_185
SR8100 = DEV_92: room: +3V_EC
SR8501 = DEV_93: room: PMIC
SR8900 SR9000-SR9003 = DEV_91: room: BL
SW2004 = DEV_158
T1101-T1106 T1610 T1611 T2005-T2013 T2301 T2302 T2706 T2707 T3005-T3008 T8001 T8304 T8318 T8319 T8801 T8802 = DEV_90: room: PMIC
T1901-T1905 T2101-T2104 T2508 T2509 T2541 T2542 T2600-T2602 T2608 T2618 T2623-T2625 T2646 T2657 T2670 T2685 T2686 T2700-T2705 T3010 T3101 T3801-T3804 T5401-T5407 T5807 T8101-T8107 T8403 T8405-T8407 T8410 T8411 T8425 T8426 T8428 T8430 T8431 T8464 T8501-T8507 T8800 = DEV_88: room: +3V_EC
T3002 T3003 T8002 T8004-T8006 = DEV_90
T8100 = DEV_89: room: 5V
T8201-T8207 T8305-T8317 T8320-T8323 T8415-T8420 = DEV_88: room: PMIC
T8902-T8907 = DEV_89: room: GASG
U1001 = DEV_182
U1101 = DEV_172
U1601 U1701 = DEV_181
U1915 = DEV_169
U2101 U8102 = DEV_54
U2301 = DEV_175
U2400 = DEV_60
U3001 = DEV_87
U3301 = DEV_165
U3302 = DEV_61
U3304 = DEV_30
U5101 = DEV_86
U5203 = DEV_160
U5401 = DEV_85
U5801 = DEV_84
U5803 = DEV_83
U5804 = DEV_82
U5806 = DEV_81
U7107 = DEV_80
U7112 = DEV_192
U7141 U7311 = DEV_79
U7320 U7322 = DEV_174
U7321 = DEV_173
U7903 = DEV_171
U7911 U7913 = DEV_78
U7920-U7922 = DEV_77
U7931 U7932 = DEV_76
U7942 = DEV_180
U8100 = DEV_75
U8101 = DEV_168
U8201 = DEV_167
U8800 = DEV_74: room: CHG
U8901 = DEV_73: room: GASG
U9000 = DEV_72: room: BL
X2600 = DEV_71
X2601 = DEV_186

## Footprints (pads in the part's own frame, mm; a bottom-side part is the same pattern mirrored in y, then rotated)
1MM_OPEN_5MIL_M1M2
  custom 0.159x0.159 smd: 1(0,-0.318) 2(0,0.318)
2MM_OPEN_5MIL_M1M2
  custom 0.318x0.318 smd: 1(0,-0.699) 2(0,0.699)
HH_H_R276X277D79N_M2_P2_V4
  round 2.007 hole 2.007 unplated: (0,0)
  round 0.61 hole 0.305: 2(0,2.2) 3(2.2,0) 4(0,-2.2) 5(-2.2,0)
HH_H_RC262X258D79N_P2_V4
  round 2.007 hole 2.007 unplated: (0,0)
  round 0.61 hole 0.305: 2(0.003,1.948) 3(1.948,-0.003) 4(-0.003,-1.948) 5(-1.948,0.003)
HH_PWR_FB_SHORT_PT
  rect 0.229x0.635 smd: 1(-0.203,0) 2(0.203,0)
HH_R0402_SHORT_12MIL
  rect 0.457x0.508 smd: 1(-0.419,0) 2(0.419,0)
HOLE_C106D106N
  round 2.692 hole 2.692 unplated: (0,0)
HOLE_CRT262X204D79
  custom 1.295x1.295 hole 2.007: 1(0,0)
HOLE_O118X106DO118X106N
  oval 2.997x2.692 hole 2.692 unplated: (0,0)
NB_PWR_FB_SHORT_PT
  rect 0.229x0.635 smd: 1(-0.203,0) 2(0.203,0)
NB_R0402_SHORT
  rect 0.635x0.635 smd: 1(-0.445,0) 2(0.445,0)
NB_R0402_SHORT_5MIL_SMALL
  rect 0.457x0.508 smd: 1(-0.419,0) 2(0.419,0)
NB_SHIELD_58P_2H_2508X1831
  oval 2.489x0.508 hole 0.508 unplated: (-34.687,-16.962)
  oval 0.508x2.489 hole 0.508 unplated: (23.963,27.688)
  rect 2.489x0.61 smd: 1(-31.187,-16.962) 2(-27.687,-16.962) 3(-24.187,-16.962) 4(-20.687,-16.962) 5(-17.187,-16.962) 6(-13.687,-16.962) 7(-10.187,-16.962) 8(-6.687,-16.962) 9(-3.187,-16.962) 10(0.313,-16.962) 11(3.813,-16.962) 12(7.313,-16.962) 13(10.813,-16.962) 14(14.313,-16.962) 15(17.813,-16.962) 16(21.313,-16.962) 29(21.313,29.338) 30(17.813,29.338) 31(14.313,29.338) 32(10.813,29.338) 33(7.313,29.338) 34(3.813,29.338) 35(0.313,29.338) 36(-3.187,29.338) 37(-6.687,29.338) 38(-10.187,29.338) 39(-13.687,29.338) 40(-17.187,29.338) 41(-20.687,29.338) 42(-24.187,29.338) 43(-27.687,29.338) 44(-31.187,29.338) 45(-34.687,29.338)
  rect 0.61x2.489 smd: 17(23.963,-14.312) 18(23.963,-10.812) 19(23.963,-7.312) 20(23.963,-3.812) 21(23.963,-0.312) 22(23.963,3.188) 23(23.963,6.688) 24(23.963,10.188) 25(23.963,13.688) 26(23.963,17.188) 27(23.963,20.688) 28(23.963,24.188) 46(-39.537,27.688) 47(-39.537,24.188) 48(-39.537,20.688) 49(-39.537,17.188) 50(-39.537,13.688) 51(-39.537,10.188) 52(-39.537,6.688) 53(-39.537,3.188) 54(-39.537,-0.312) 55(-39.537,-3.812) 56(-39.537,-7.312) 57(-39.537,-10.812) 58(-39.537,-14.312)
NB_SHIELDING_52P_2HOLD
  oval 0.508x2.489 hole 0.508 unplated: (-27.6,19.2)
  oval 2.489x0.508 hole 0.508 unplated: (24.05,-21.95)
  rect 2.489x0.61 smd: 1(-24.95,-21.95) 2(-21.45,-21.95) 3(-17.95,-21.95) 4(-14.45,-21.95) 5(-10.95,-21.95) 6(-7.45,-21.95) 7(-3.95,-21.95) 8(-0.45,-21.95) 9(3.05,-21.95) 10(6.55,-21.95) 11(10.05,-21.95) 12(13.55,-21.95) 13(17.05,-21.95) 14(20.55,-21.95) 27(24.05,21.95) 28(20.55,21.95) 29(17.05,21.95) 30(13.55,21.95) 31(10.05,21.95) 32(6.55,21.95) 33(3.05,21.95) 34(-0.45,21.95) 35(-3.95,21.95) 36(-7.45,21.95) 37(-10.95,21.95) 38(-14.45,21.95) 39(-17.95,21.95) 40(-21.45,21.95) 41(-24.95,21.95)
  rect 0.61x2.489 smd: 15(27.7,-19.2) 16(27.7,-15.7) 17(27.7,-12.2) 18(27.7,-8.7) 19(27.7,-5.2) 20(27.7,-1.7) 21(27.7,1.8) 22(27.7,5.3) 23(27.7,8.8) 24(27.7,12.3) 25(27.7,15.8) 26(27.7,19.3) 42(-27.6,15.7) 43(-27.6,12.2) 44(-27.6,8.7) 45(-27.6,5.2) 46(-27.6,1.7) 47(-27.6,-1.8) 48(-27.6,-5.3) 49(-27.6,-8.8) 50(-27.6,-12.3) 51(-27.6,-15.8) 52(-27.6,-19.3)
NB_TPC22T_68
  round 0.559 smd: 1(0,0)
NB_TPC26T_68
  round 0.66 smd: 1(0,0)
NB_TPC28T_68
  round 0.711 smd: 1(0,0)
R0402
  rect 0.432x0.508 smd: 1(-0.432,0) 2(0.432,0)
R0603
  rect 0.559x0.889 smd: 1(-0.67,0) 2(0.67,0)
SMD79X157_NP
  rect 2.007x3.988 smd: 1(0,0)
SMDPAD79X315_NP
  rect 2.007x8.001 smd: 1(0,0)
SMDPAD_394X394_NP
  rect 10.008x10.008 smd: 1(0,0)
T_CSP_15P_20_103X77
  round 0.254 smd: A1(-1,-0.5) A2(-1,0) A3(-1,0.5) B1(-0.5,-0.5) B2(-0.5,0) B3(-0.5,0.5) C1(0,-0.5) C2(0,0) C3(0,0.5) D1(0.5,-0.5) D2(0.5,0) D3(0.5,0.5) E1(1,-0.5) E2(1,0) E3(1,0.5)
T_HH_BGA_1380P_669X669
  round 0.229 smd: A3(7.357,-7.998) A5(6.791,-7.998) A7(6.225,-7.998) A53(-6.225,-7.998) A55(-6.791,-7.998) A57(-7.357,-7.998) AA3(7.357,-2.264) AA5(6.791,-2.264) AA7(6.225,-2.264) AA9(5.659,-2.264) AA11(5.093,-2.264) AA49(-5.093,-2.264) AA51(-5.659,-2.264) AA53(-6.225,-2.264) AA55(-6.791,-2.264) AA57(-7.357,-2.264) AB4(7.074,-1.981) AB6(6.508,-1.981) AB8(5.942,-1.981) AB10(5.376,-1.981) AB12(4.81,-1.981) AB48(-4.81,-1.981) AB50(-5.376,-1.981) AB52(-5.942,-1.981) AB54(-6.508,-1.981) AB56(-7.074,-1.981) AC3(7.357,-1.698) AC5(6.791,-1.698) AC7(6.225,-1.698) AC9(5.659,-1.698) AC11(5.093,-1.698) AC49(-5.093,-1.698) AC51(-5.659,-1.698) AC53(-6.225,-1.698) AC55(-6.791,-1.698) AC57(-7.357,-1.698) AD2(7.715,-1.415) AD4(7.074,-1.415) AD6(6.508,-1.415) AD8(5.942,-1.415) AD10(5.376,-1.415) AD12(4.81,-1.415) AD48(-4.81,-1.415) AD50(-5.376,-1.415) AD52(-5.942,-1.415) AD54(-6.508,-1.415) AD56(-7.074,-1.415) AD58(-7.715,-1.415) AE3(7.394,-1.169) AE5(6.791,-1.132) AE7(6.225,-1.132) AE9(5.659,-1.132) AE11(5.093,-1.132) AE49(-5.093,-1.132) AE51(-5.659,-1.132) AE53(-6.225,-1.132) AE55(-6.791,-1.132) AE57(-7.394,-1.169) AF4(7.074,-0.849) AF6(6.508,-0.849) AF8(5.942,-0.849) AF10(5.376,-0.849) AF12(4.81,-0.849) AF48(-4.81,-0.849) AF50(-5.376,-0.849) AF52(-5.942,-0.849) AF54(-6.508,-0.849) AF56(-7.074,-0.849) AG3(7.394,-0.529) AG5(6.791,-0.566) AG7(6.225,-0.566) AG9(5.659,-0.566) AG11(5.093,-0.566) AG49(-5.093,-0.566) AG51(-5.659,-0.566) AG53(-6.225,-0.566) AG55(-6.791,-0.566) AG57(-7.394,-0.529) AH2(7.715,-0.283) AH4(7.074,-0.283) AH6(6.508,-0.283) AH8(5.942,-0.283) AH10(5.376,-0.283) AH12(4.81,-0.283) AH48(-4.81,-0.283) AH50(-5.376,-0.283) AH52(-5.942,-0.283) AH54(-6.508,-0.283) AH56(-7.074,-0.283) AH58(-7.715,-0.283) AK3(7.357,0) AK5(6.791,0) AK7(6.225,0) AK9(5.659,0) AK11(5.093,0) AK49(-5.093,0) AK51(-5.659,0) AK53(-6.225,0) AK55(-6.791,0) AK57(-7.357,0) AM2(7.715,0.283) AM4(7.074,0.283) AM6(6.508,0.283) AM8(5.942,0.283) AM10(5.376,0.283) AM12(4.81,0.283) AM48(-4.81,0.283) AM50(-5.376,0.283) AM52(-5.942,0.283) AM54(-6.508,0.283) AM56(-7.074,0.283) AM58(-7.715,0.283) AN3(7.394,0.529) AN5(6.791,0.566) AN7(6.225,0.566) AN9(5.659,0.566) AN11(5.093,0.566) AN49(-5.093,0.566) AN51(-5.659,0.566) AN53(-6.225,0.566) AN55(-6.791,0.566) AN57(-7.394,0.529) AP4(7.074,0.849) AP6(6.508,0.849) AP8(5.942,0.849) AP10(5.376,0.849) AP12(4.81,0.849) AP48(-4.81,0.849) AP50(-5.376,0.849) AP52(-5.942,0.849) AP54(-6.508,0.849) AP56(-7.074,0.849) AR3(7.394,1.169) AR5(6.791,1.132) AR7(6.225,1.132) AR9(5.659,1.132) AR11(5.093,1.132) AR49(-5.093,1.132) AR51(-5.659,1.132) AR53(-6.225,1.132) AR55(-6.791,1.132) AR57(-7.394,1.169) AT2(7.715,1.415) AT4(7.074,1.415) AT6(6.508,1.415) AT8(5.942,1.415) AT10(5.376,1.415) AT12(4.81,1.415) AT48(-4.81,1.415) AT50(-5.376,1.415) AT52(-5.942,1.415) AT54(-6.508,1.415) AT56(-7.074,1.415) AT58(-7.715,1.415) AU3(7.357,1.698) AU5(6.791,1.698) AU7(6.225,1.698) AU9(5.659,1.698) AU11(5.093,1.698) AU49(-5.093,1.698) AU51(-5.659,1.698) AU53(-6.225,1.698) AU55(-6.791,1.698) AU57(-7.357,1.698) AV4(7.074,1.981) AV6(6.508,1.981) AV8(5.942,1.981) AV10(5.376,1.981) AV12(4.81,1.981) AV48(-4.81,1.981) AV50(-5.376,1.981) AV52(-5.942,1.981) AV54(-6.508,1.981) AV56(-7.074,1.981) AW3(7.357,2.264) AW5(6.791,2.264) AW7(6.225,2.264) AW9(5.659,2.264) AW11(5.093,2.264) AW49(-5.093,2.264) AW51(-5.659,2.264) AW53(-6.225,2.264) AW55(-6.791,2.264) AW57(-7.357,2.264) AY2(7.715,2.547) AY4(7.074,2.547) AY6(6.508,2.547) AY8(5.942,2.547) AY10(5.376,2.547) AY12(4.81,2.547) AY48(-4.81,2.547) AY50(-5.376,2.547) AY52(-5.942,2.547) AY54(-6.508,2.547) AY56(-7.074,2.547) AY58(-7.715,2.547) B2(7.64,-7.64) B4(7.074,-7.715) B6(6.508,-7.64) B8(5.942,-7.715) B12(4.81,-7.715) B16(3.678,-7.715) B20(2.547,-7.715) B24(1.415,-7.715) B28(0.283,-7.715) B34(-0.849,-7.715) B38(-1.981,-7.715) B42(-3.113,-7.715) B46(-4.244,-7.715) B50(-5.376,-7.715) B54(-6.508,-7.715) B56(-7.074,-7.64) B58(-7.64,-7.64) BA3(7.394,2.792) BA5(6.791,2.83) BA7(6.225,2.83) BA9(5.659,2.83) BA11(5.093,2.83) BA49(-5.093,2.83) BA51(-5.659,2.83) BA53(-6.225,2.83) BA55(-6.791,2.83) BA57(-7.394,2.792) BB4(7.074,3.113) BB6(6.508,3.113) BB8(5.942,3.113) BB10(5.376,3.113) BB12(4.81,3.113) BB48(-4.81,3.113) BB50(-5.376,3.113) BB52(-5.942,3.113) BB54(-6.508,3.113) BB56(-7.074,3.113) BC3(7.394,3.433) BC5(6.791,3.395) BC7(6.225,3.395) BC9(5.659,3.395) BC11(5.093,3.395) BC49(-5.093,3.395) BC51(-5.659,3.395) BC53(-6.225,3.395) BC55(-6.791,3.395) BC57(-7.394,3.433) BD2(7.715,3.678) BD4(7.074,3.678) BD6(6.508,3.678) BD8(5.942,3.678) BD10(5.376,3.678) BD12(4.81,3.678) BD48(-4.81,3.678) BD50(-5.376,3.678) BD52(-5.942,3.678) BD54(-6.508,3.678) BD56(-7.074,3.678) BD58(-7.715,3.678) BE3(7.357,3.961) BE5(6.791,3.961) BE7(6.225,3.961) BE9(5.659,3.961) BE11(5.093,3.961) BE49(-5.093,3.961) BE51(-5.659,3.961) BE53(-6.225,3.961) BE55(-6.791,3.961) BE57(-7.357,3.961) BF4(7.074,4.244) BF6(6.508,4.244) BF8(5.942,4.244) BF10(5.376,4.244) BF12(4.81,4.244) BF48(-4.81,4.244) BF50(-5.376,4.244) BF52(-5.942,4.244) BF54(-6.508,4.244) BF56(-7.074,4.244) BG3(7.357,4.527) BG5(6.791,4.527) BG7(6.225,4.527) BG9(5.659,4.527) BG11(5.093,4.527) BG49(-5.093,4.527) BG51(-5.659,4.527) BG53(-6.225,4.527) BG55(-6.791,4.527) BG57(-7.357,4.527) BH2(7.715,4.81) BH4(7.074,4.81) BH6(6.508,4.81) BH8(5.942,4.81) BH10(5.376,4.81) BH12(4.81,4.81) BH14(4.244,4.81) BH16(3.678,4.81) BH18(3.113,4.81) BH20(2.547,4.81) BH22(1.981,4.81) BH24(1.415,4.81) BH26(0.849,4.81) BH28(0.283,4.81) BH32(-0.283,4.81) BH34(-0.849,4.81) BH36(-1.415,4.81) BH38(-1.981,4.81) BH40(-2.547,4.81) BH42(-3.113,4.81) BH44(-3.678,4.81) BH46(-4.244,4.81) BH48(-4.81,4.81) BH50(-5.376,4.81) BH52(-5.942,4.81) BH54(-6.508,4.81) BH56(-7.074,4.81) BH58(-7.715,4.81) BJ3(7.394,5.056) BJ5(6.791,5.093) BJ7(6.225,5.093) BJ9(5.659,5.093) BJ11(5.093,5.093) BJ13(4.527,5.093) BJ15(3.961,5.093) BJ17(3.395,5.093) BJ19(2.83,5.093) BJ21(2.264,5.093) BJ23(1.698,5.093) BJ25(1.132,5.093) BJ27(0.566,5.093) BJ30(0,5.093) BJ33(-0.566,5.093) BJ35(-1.132,5.093) BJ37(-1.698,5.093) BJ39(-2.264,5.093) BJ41(-2.83,5.093) BJ43(-3.395,5.093) BJ45(-3.961,5.093) BJ47(-4.527,5.093) BJ49(-5.093,5.093) BJ51(-5.659,5.093) BJ53(-6.225,5.093) BJ55(-6.791,5.093) BJ57(-7.394,5.056) BK4(7.074,5.376) BK6(6.508,5.376) BK8(5.942,5.376) BK10(5.376,5.376) BK12(4.81,5.376) BK14(4.244,5.376) BK16(3.678,5.376) BK18(3.113,5.376) BK20(2.547,5.376) BK22(1.981,5.376) BK24(1.415,5.376) BK26(0.849,5.376) BK28(0.283,5.376) BK32(-0.283,5.376) BK34(-0.849,5.376) BK36(-1.415,5.376) BK38(-1.981,5.376) BK40(-2.547,5.376) BK42(-3.113,5.376) BK44(-3.678,5.376) BK46(-4.244,5.376) BK48(-4.81,5.376) BK50(-5.376,5.376) BK52(-5.942,5.376) BK54(-6.508,5.376) BK56(-7.074,5.376) BL3(7.394,5.696) BL5(6.791,5.659) BL7(6.225,5.659) BL9(5.659,5.659) BL11(5.093,5.659) BL13(4.527,5.659) BL15(3.961,5.659) BL17(3.395,5.659) BL19(2.83,5.659) BL21(2.264,5.659) BL23(1.698,5.659) BL25(1.132,5.659) BL27(0.566,5.659) BL30(0,5.659) BL33(-0.566,5.659) BL35(-1.132,5.659) BL37(-1.698,5.659) BL39(-2.264,5.659) BL41(-2.83,5.659) BL43(-3.395,5.659) BL45(-3.961,5.659) BL47(-4.527,5.659) BL49(-5.093,5.659) BL51(-5.659,5.659) BL53(-6.225,5.659) BL55(-6.791,5.659) BL57(-7.394,5.696) BM2(7.715,5.942) BM4(7.074,5.942) BM6(6.508,5.942) BM8(5.942,5.942) BM10(5.376,5.942) BM12(4.81,5.942) BM14(4.244,5.942) BM16(3.678,5.942) BM18(3.113,5.942) BM20(2.547,5.942) BM22(1.981,5.942) BM24(1.415,5.942) BM26(0.849,5.942) BM28(0.283,5.942) BM32(-0.283,5.942) BM34(-0.849,5.942) BM36(-1.415,5.942) BM38(-1.981,5.942) BM40(-2.547,5.942) BM42(-3.113,5.942) BM44(-3.678,5.942) BM46(-4.244,5.942) BM48(-4.81,5.942) BM50(-5.376,5.942) BM52(-5.942,5.942) BM54(-6.508,5.942) BM56(-7.074,5.942) BM58(-7.715,5.942) BN1(7.998,6.225) BN3(7.357,6.225) BN5(6.791,6.225) BN7(6.225,6.225) BN9(5.659,6.225) BN11(5.093,6.225) BN13(4.527,6.225) BN15(3.961,6.225) BN17(3.395,6.225) BN19(2.83,6.225) BN21(2.264,6.225) BN23(1.698,6.225) BN25(1.132,6.225) BN27(0.566,6.225) BN30(0,6.225) BN33(-0.566,6.225) BN35(-1.132,6.225) BN37(-1.698,6.225) BN39(-2.264,6.225) BN41(-2.83,6.225) BN43(-3.395,6.225) BN45(-3.961,6.225) BN47(-4.527,6.225) BN49(-5.093,6.225) BN51(-5.659,6.225) BN53(-6.225,6.225) BN55(-6.791,6.225) BN57(-7.357,6.225) BN59(-7.998,6.225) BP2(7.64,6.508) BP4(7.074,6.508) BP6(6.508,6.508) BP8(5.942,6.508) BP10(5.376,6.508) BP12(4.81,6.508) BP14(4.244,6.508) BP16(3.678,6.508) BP18(3.113,6.508) BP20(2.547,6.508) BP22(1.981,6.508) BP24(1.415,6.508) BP26(0.849,6.508) BP28(0.283,6.508) BP32(-0.283,6.508) BP34(-0.849,6.508) BP36(-1.415,6.508) BP38(-1.981,6.508) BP40(-2.547,6.508) BP42(-3.113,6.508) BP44(-3.678,6.508) BP46(-4.244,6.508) BP48(-4.81,6.508) BP50(-5.376,6.508) BP52(-5.942,6.508) BP54(-6.508,6.508) BP56(-7.074,6.508) BP58(-7.64,6.508) BR1(7.998,6.791) BR3(7.357,6.791) BR5(6.791,6.791) BR7(6.225,6.791) BR9(5.659,6.791) BR11(5.093,6.791) BR13(4.527,6.791) BR15(3.961,6.791) BR17(3.395,6.791) BR19(2.83,6.791) BR21(2.264,6.791) BR23(1.698,6.791) BR25(1.132,6.791) BR27(0.566,6.791) BR30(0,6.791) BR33(-0.566,6.791) BR35(-1.132,6.791) BR37(-1.698,6.791) BR39(-2.264,6.791) BR41(-2.83,6.791) BR43(-3.395,6.791) BR45(-3.961,6.791) BR47(-4.527,6.791) BR49(-5.093,6.791) BR51(-5.659,6.791) BR53(-6.225,6.791) BR55(-6.791,6.791) BR57(-7.357,6.791) BR59(-7.998,6.791) BT2(7.715,7.074) BT4(7.074,7.074) BT6(6.508,7.074) BT8(5.942,7.074) BT10(5.376,7.074) BT12(4.81,7.074) BT14(4.244,7.074) BT16(3.678,7.074) BT18(3.113,7.074) BT20(2.547,7.074) BT22(1.981,7.074) BT24(1.415,7.074) BT26(0.849,7.074) BT28(0.283,7.074) BT32(-0.283,7.074) BT34(-0.849,7.074) BT36(-1.415,7.074) BT38(-1.981,7.074) BT40(-2.547,7.074) BT42(-3.113,7.074) BT44(-3.678,7.074) BT46(-4.244,7.074) BT48(-4.81,7.074) BT50(-5.376,7.074) BT52(-5.942,7.074) BT54(-6.508,7.074) BT56(-7.074,7.074) BT58(-7.715,7.074) BU1(7.998,7.357) BU3(7.357,7.357) BU5(6.791,7.357) BU7(6.225,7.357) BU9(5.696,7.394) BU11(5.056,7.394) BU13(4.527,7.357) BU15(3.961,7.357) BU17(3.433,7.394) BU19(2.792,7.394) BU21(2.264,7.357) BU23(1.698,7.357) BU25(1.169,7.394) BU27(0.529,7.394) BU30(0,7.357) BU33(-0.603,7.394) BU35(-1.132,7.357) BU37(-1.698,7.357) BU39(-2.227,7.394) BU41(-2.867,7.394) BU43(-3.395,7.357) BU45(-3.961,7.357) BU47(-4.49,7.394) BU49(-5.13,7.394) BU51(-5.659,7.357) BU53(-6.225,7.357) BU55(-6.791,7.357) BU57(-7.394,7.32) BU59(-7.998,7.357) BV2(7.64,7.64) BV4(7.074,7.715) BV6(6.508,7.64) BV8(5.942,7.715) BV12(4.81,7.715) BV16(3.678,7.715) BV20(2.547,7.715) BV24(1.415,7.715) BV28(0.283,7.715) BV34(-0.849,7.715) BV38(-1.981,7.715) BV42(-3.113,7.715) BV46(-4.244,7.715) BV50(-5.376,7.715) BV54(-6.508,7.715) BV56(-7.074,7.64) BV58(-7.64,7.64) BW3(7.357,7.998) BW5(6.791,7.998) BW7(6.225,7.998) BW53(-6.225,7.998) BW55(-6.791,7.998) BW57(-7.357,7.998) C1(7.998,-7.357) C3(7.357,-7.357) C5(6.791,-7.357) C7(6.225,-7.357) C9(5.696,-7.394) C11(5.056,-7.394) C13(4.527,-7.357) C15(3.961,-7.357) C17(3.433,-7.394) C19(2.792,-7.394) C21(2.264,-7.357) C23(1.698,-7.357) C25(1.169,-7.394) C27(0.529,-7.394) C30(0,-7.357) C33(-0.603,-7.394) C35(-1.132,-7.357) C37(-1.698,-7.357) C39(-2.227,-7.394) C41(-2.867,-7.394) C43(-3.395,-7.357) C45(-3.961,-7.357) C47(-4.49,-7.394) C49(-5.13,-7.394) C51(-5.659,-7.357) C53(-6.225,-7.357) C55(-6.791,-7.357) C57(-7.394,-7.32) C59(-7.998,-7.357) D2(7.715,-7.074) D4(7.074,-7.074) D6(6.508,-7.074) D8(5.942,-7.074) D10(5.376,-7.074) D12(4.81,-7.074) D14(4.244,-7.074) D16(3.678,-7.074) D18(3.113,-7.074) D20(2.547,-7.074) D22(1.981,-7.074) D24(1.415,-7.074) D26(0.849,-7.074) D28(0.283,-7.074) D32(-0.283,-7.074) D34(-0.849,-7.074) D36(-1.415,-7.074) D38(-1.981,-7.074) D40(-2.547,-7.074) D42(-3.113,-7.074) D44(-3.678,-7.074) D46(-4.244,-7.074) D48(-4.81,-7.074) D50(-5.376,-7.074) D52(-5.942,-7.074) D54(-6.508,-7.074) D56(-7.074,-7.074) D58(-7.715,-7.074) E1(7.998,-6.791) E3(7.357,-6.791) E5(6.791,-6.791) E7(6.225,-6.791) E9(5.659,-6.791) E11(5.093,-6.791) E13(4.527,-6.791) E15(3.961,-6.791) E17(3.395,-6.791) E19(2.83,-6.791) E21(2.264,-6.791) E23(1.698,-6.791) E25(1.132,-6.791) E27(0.566,-6.791) E30(0,-6.791) E33(-0.566,-6.791) E35(-1.132,-6.791) E37(-1.698,-6.791) E39(-2.264,-6.791) E41(-2.83,-6.791) E43(-3.395,-6.791) E45(-3.961,-6.791) E47(-4.527,-6.791) E49(-5.093,-6.791) E51(-5.659,-6.791) E53(-6.225,-6.791) E55(-6.791,-6.791) E57(-7.357,-6.791) E59(-7.998,-6.791) F2(7.64,-6.508) F4(7.074,-6.508) F6(6.508,-6.508) F8(5.942,-6.508) F10(5.376,-6.508) F12(4.81,-6.508) F14(4.244,-6.508) F16(3.678,-6.508) F18(3.113,-6.508) F20(2.547,-6.508) F22(1.981,-6.508) F24(1.415,-6.508) F26(0.849,-6.508) F28(0.283,-6.508) F32(-0.283,-6.508) F34(-0.849,-6.508) F36(-1.415,-6.508) F38(-1.981,-6.508) F40(-2.547,-6.508) F42(-3.113,-6.508) F44(-3.678,-6.508) F46(-4.244,-6.508) F48(-4.81,-6.508) F50(-5.376,-6.508) F52(-5.942,-6.508) F54(-6.508,-6.508) F56(-7.074,-6.508) F58(-7.64,-6.508) G1(7.998,-6.225) G3(7.357,-6.225) G5(6.791,-6.225) G7(6.225,-6.225) G9(5.659,-6.225) G11(5.093,-6.225) G13(4.527,-6.225) G15(3.961,-6.225) G17(3.395,-6.225) G19(2.83,-6.225) G21(2.264,-6.225) G23(1.698,-6.225) G25(1.132,-6.225) G27(0.566,-6.225) G30(0,-6.225) G33(-0.566,-6.225) G35(-1.132,-6.225) G37(-1.698,-6.225) G39(-2.264,-6.225) G41(-2.83,-6.225) G43(-3.395,-6.225) G45(-3.961,-6.225) G47(-4.527,-6.225) G49(-5.093,-6.225) G51(-5.659,-6.225) G53(-6.225,-6.225) G55(-6.791,-6.225) G57(-7.357,-6.225) G59(-7.998,-6.225) H2(7.715,-5.942) H4(7.074,-5.942) H6(6.508,-5.942) H8(5.942,-5.942) H10(5.376,-5.942) H12(4.81,-5.942) H14(4.244,-5.942) H16(3.678,-5.942) H18(3.113,-5.942) H20(2.547,-5.942) H22(1.981,-5.942) H24(1.415,-5.942) H26(0.849,-5.942) H28(0.283,-5.942) H32(-0.283,-5.942) H34(-0.849,-5.942) H36(-1.415,-5.942) H38(-1.981,-5.942) H40(-2.547,-5.942) H42(-3.113,-5.942) H44(-3.678,-5.942) H46(-4.244,-5.942) H48(-4.81,-5.942) H50(-5.376,-5.942) H52(-5.942,-5.942) H54(-6.508,-5.942) H56(-7.074,-5.942) H58(-7.715,-5.942) J3(7.394,-5.696) J5(6.791,-5.659) J7(6.225,-5.659) J9(5.659,-5.659) J11(5.093,-5.659) J13(4.527,-5.659) J15(3.961,-5.659) J17(3.395,-5.659) J19(2.83,-5.659) J21(2.264,-5.659) J23(1.698,-5.659) J25(1.132,-5.659) J27(0.566,-5.659) J30(0,-5.659) J33(-0.566,-5.659) J35(-1.132,-5.659) J37(-1.698,-5.659) J39(-2.264,-5.659) J41(-2.83,-5.659) J43(-3.395,-5.659) J45(-3.961,-5.659) J47(-4.527,-5.659) J49(-5.093,-5.659) J51(-5.659,-5.659) J53(-6.225,-5.659) J55(-6.791,-5.659) J57(-7.394,-5.696) K4(7.074,-5.376) K6(6.508,-5.376) K8(5.942,-5.376) K10(5.376,-5.376) K12(4.81,-5.376) K14(4.244,-5.376) K16(3.678,-5.376) K18(3.113,-5.376) K20(2.547,-5.376) K22(1.981,-5.376) K24(1.415,-5.376) K26(0.849,-5.376) K28(0.283,-5.376) K32(-0.283,-5.376) K34(-0.849,-5.376) K36(-1.415,-5.376) K38(-1.981,-5.376) K40(-2.547,-5.376) K42(-3.113,-5.376) K44(-3.678,-5.376) K46(-4.244,-5.376) K48(-4.81,-5.376) K50(-5.376,-5.376) K52(-5.942,-5.376) K54(-6.508,-5.376) K56(-7.074,-5.376) L3(7.394,-5.056) L5(6.791,-5.093) L7(6.225,-5.093) L9(5.659,-5.093) L11(5.093,-5.093) L13(4.527,-5.093) L15(3.961,-5.093) L17(3.395,-5.093) L19(2.83,-5.093) L21(2.264,-5.093) L23(1.698,-5.093) L25(1.132,-5.093) L27(0.566,-5.093) L30(0,-5.093) L33(-0.566,-5.093) L35(-1.132,-5.093) L37(-1.698,-5.093) L39(-2.264,-5.093) L41(-2.83,-5.093) L43(-3.395,-5.093) L45(-3.961,-5.093) L47(-4.527,-5.093) L49(-5.093,-5.093) L51(-5.659,-5.093) L53(-6.225,-5.093) L55(-6.791,-5.093) L57(-7.394,-5.056) M2(7.715,-4.81) M4(7.074,-4.81) M6(6.508,-4.81) M8(5.942,-4.81) M10(5.376,-4.81) M12(4.81,-4.81) M14(4.244,-4.81) M16(3.678,-4.81) M18(3.113,-4.81) M20(2.547,-4.81) M22(1.981,-4.81) M24(1.415,-4.81) M26(0.849,-4.81) M28(0.283,-4.81) M32(-0.283,-4.81) M34(-0.849,-4.81) M36(-1.415,-4.81) M38(-1.981,-4.81) M40(-2.547,-4.81) M42(-3.113,-4.81) M44(-3.678,-4.81) M46(-4.244,-4.81) M48(-4.81,-4.81) M50(-5.376,-4.81) M52(-5.942,-4.81) M54(-6.508,-4.81) M56(-7.074,-4.81) M58(-7.715,-4.81) N3(7.357,-4.527) N5(6.791,-4.527) N7(6.225,-4.527) N9(5.659,-4.527) N11(5.093,-4.527) N49(-5.093,-4.527) N51(-5.659,-4.527) N53(-6.225,-4.527) N55(-6.791,-4.527) N57(-7.357,-4.527) P4(7.074,-4.244) P6(6.508,-4.244) P8(5.942,-4.244) P10(5.376,-4.244) P12(4.81,-4.244) P48(-4.81,-4.244) P50(-5.376,-4.244) P52(-5.942,-4.244) P54(-6.508,-4.244) P56(-7.074,-4.244) R3(7.357,-3.961) R5(6.791,-3.961) R7(6.225,-3.961) R9(5.659,-3.961) R11(5.093,-3.961) R49(-5.093,-3.961) R51(-5.659,-3.961) R53(-6.225,-3.961) R55(-6.791,-3.961) R57(-7.357,-3.961) T2(7.715,-3.678) T4(7.074,-3.678) T6(6.508,-3.678) T8(5.942,-3.678) T10(5.376,-3.678) T12(4.81,-3.678) T48(-4.81,-3.678) T50(-5.376,-3.678) T52(-5.942,-3.678) T54(-6.508,-3.678) T56(-7.074,-3.678) T58(-7.715,-3.678) U3(7.394,-3.433) U5(6.791,-3.395) U7(6.225,-3.395) U9(5.659,-3.395) U11(5.093,-3.395) U49(-5.093,-3.395) U51(-5.659,-3.395) U53(-6.225,-3.395) U55(-6.791,-3.395) U57(-7.394,-3.433) V4(7.074,-3.113) V6(6.508,-3.113) V8(5.942,-3.113) V10(5.376,-3.113) V12(4.81,-3.113) V48(-4.81,-3.113) V50(-5.376,-3.113) V52(-5.942,-3.113) V54(-6.508,-3.113) V56(-7.074,-3.113) W3(7.394,-2.792) W5(6.791,-2.83) W7(6.225,-2.83) W9(5.659,-2.83) W11(5.093,-2.83) W49(-5.093,-2.83) W51(-5.659,-2.83) W53(-6.225,-2.83) W55(-6.791,-2.83) W57(-7.394,-2.792) Y2(7.715,-2.547) Y4(7.074,-2.547) Y6(6.508,-2.547) Y8(5.942,-2.547) Y10(5.376,-2.547) Y12(4.81,-2.547) Y48(-4.81,-2.547) Y50(-5.376,-2.547) Y52(-5.942,-2.547) Y54(-6.508,-2.547) Y56(-7.074,-2.547) Y58(-7.715,-2.547)
  round 0.33 smd: A9(5.659,-7.998) A11(5.093,-7.998) A13(4.527,-7.998) A15(3.961,-7.998) A17(3.395,-7.998) A19(2.83,-7.998) A21(2.264,-7.998) A23(1.698,-7.998) A25(1.132,-7.998) A27(0.566,-7.998) A30(0,-7.998) A33(-0.566,-7.998) A35(-1.132,-7.998) A37(-1.698,-7.998) A39(-2.264,-7.998) A41(-2.83,-7.998) A43(-3.395,-7.998) A45(-3.961,-7.998) A47(-4.527,-7.998) A49(-5.093,-7.998) A51(-5.659,-7.998) AA1(7.998,-2.264) AA59(-7.998,-2.264) AB2(7.64,-1.981) AB58(-7.64,-1.981) AC1(7.998,-1.698) AC59(-7.998,-1.698) AE1(7.998,-1.132) AE59(-7.998,-1.132) AF2(7.64,-0.849) AF58(-7.64,-0.849) AG1(7.998,-0.566) AG59(-7.998,-0.566) AK1(7.998,0) AK59(-7.998,0) AN1(7.998,0.566) AN59(-7.998,0.566) AP2(7.64,0.849) AP58(-7.64,0.849) AR1(7.998,1.132) AR59(-7.998,1.132) AU1(7.998,1.698) AU59(-7.998,1.698) AV2(7.64,1.981) AV58(-7.64,1.981) AW1(7.998,2.264) AW59(-7.998,2.264) B10(5.376,-7.64) B14(4.244,-7.64) B18(3.113,-7.64) B22(1.981,-7.64) B26(0.849,-7.64) B32(-0.283,-7.64) B36(-1.415,-7.64) B40(-2.547,-7.64) B44(-3.678,-7.64) B48(-4.81,-7.64) B52(-5.942,-7.64) BA1(7.998,2.83) BA59(-7.998,2.83) BB2(7.64,3.113) BB58(-7.64,3.113) BC1(7.998,3.395) BC59(-7.998,3.395) BE1(7.998,3.961) BE59(-7.998,3.961) BF2(7.64,4.244) BF58(-7.64,4.244) BG1(7.998,4.527) BG59(-7.998,4.527) BJ1(7.998,5.093) BJ59(-7.998,5.093) BK2(7.64,5.376) BK58(-7.64,5.376) BL1(7.998,5.659) BL59(-7.998,5.659) BV10(5.376,7.64) BV14(4.244,7.64) BV18(3.113,7.64) BV22(1.981,7.64) BV26(0.849,7.64) BV32(-0.283,7.64) BV36(-1.415,7.64) BV40(-2.547,7.64) BV44(-3.678,7.64) BV48(-4.81,7.64) BV52(-5.942,7.64) BW9(5.659,7.998) BW11(5.093,7.998) BW13(4.527,7.998) BW15(3.961,7.998) BW17(3.395,7.998) BW19(2.83,7.998) BW21(2.264,7.998) BW23(1.698,7.998) BW25(1.132,7.998) BW27(0.566,7.998) BW30(0,7.998) BW33(-0.566,7.998) BW35(-1.132,7.998) BW37(-1.698,7.998) BW39(-2.264,7.998) BW41(-2.83,7.998) BW43(-3.395,7.998) BW45(-3.961,7.998) BW47(-4.527,7.998) BW49(-5.093,7.998) BW51(-5.659,7.998) J1(7.998,-5.659) J59(-7.998,-5.659) K2(7.64,-5.376) K58(-7.64,-5.376) L1(7.998,-5.093) L59(-7.998,-5.093) N1(7.998,-4.527) N59(-7.998,-4.527) P2(7.64,-4.244) P58(-7.64,-4.244) R1(7.998,-3.961) R59(-7.998,-3.961) U1(7.998,-3.395) U59(-7.998,-3.395) V2(7.64,-3.113) V58(-7.64,-3.113) W1(7.998,-2.83) W59(-7.998,-2.83)
  round 0.279 smd: AA15(3.989,-2.383) AA17(3.439,-2.383) AA19(2.888,-2.383) AA21(2.338,-2.383) AA23(1.788,-2.383) AA25(1.238,-2.383) AA27(0.688,-2.383) AA29(0.137,-2.383) AA32(-0.413,-2.383) AA34(-0.963,-2.383) AA36(-1.513,-2.383) AA38(-2.063,-2.383) AA40(-2.614,-2.383) AA42(-3.164,-2.383) AA44(-3.714,-2.383) AA46(-4.264,-2.383) AC14(4.264,-1.906) AC16(3.714,-1.906) AC18(3.164,-1.906) AC20(2.613,-1.906) AC22(2.063,-1.906) AC24(1.513,-1.906) AC26(0.963,-1.906) AC28(0.412,-1.906) AC31(-0.138,-1.906) AC33(-0.688,-1.906) AC35(-1.238,-1.906) AC37(-1.788,-1.906) AC39(-2.339,-1.906) AC41(-2.889,-1.906) AC43(-3.439,-1.906) AC45(-3.989,-1.906) AD15(3.989,-1.43) AD17(3.439,-1.43) AD19(2.888,-1.43) AD21(2.338,-1.43) AD23(1.788,-1.43) AD25(1.238,-1.43) AD27(0.688,-1.43) AD29(0.137,-1.43) AD32(-0.413,-1.43) AD34(-0.963,-1.43) AD36(-1.513,-1.43) AD38(-2.063,-1.43) AD40(-2.614,-1.43) AD42(-3.164,-1.43) AD44(-3.714,-1.43) AD46(-4.264,-1.43) AF14(4.264,-0.953) AF16(3.714,-0.953) AF18(3.164,-0.953) AF20(2.613,-0.953) AF22(2.063,-0.953) AF24(1.513,-0.953) AF26(0.963,-0.953) AF28(0.412,-0.953) AF31(-0.138,-0.953) AF33(-0.688,-0.953) AF35(-1.238,-0.953) AF37(-1.788,-0.953) AF39(-2.339,-0.953) AF41(-2.889,-0.953) AF43(-3.439,-0.953) AF45(-3.989,-0.953) AH15(3.989,-0.477) AH17(3.439,-0.477) AH19(2.888,-0.477) AH21(2.338,-0.477) AH23(1.788,-0.477) AH25(1.238,-0.477) AH27(0.688,-0.477) AH29(0.137,-0.477) AH32(-0.413,-0.477) AH34(-0.963,-0.477) AH36(-1.513,-0.477) AH38(-2.063,-0.477) AH40(-2.614,-0.477) AH42(-3.164,-0.477) AH44(-3.714,-0.477) AH46(-4.264,-0.477) AK14(4.264,0) AK16(3.714,0) AK18(3.164,0) AK20(2.613,0) AK22(2.063,0) AK24(1.513,0) AK26(0.963,0) AK28(0.412,0) AK31(-0.138,0) AK33(-0.688,0) AK35(-1.238,0) AK37(-1.788,0) AK39(-2.339,0) AK41(-2.889,0) AK43(-3.439,0) AK45(-3.989,0) AM15(3.989,0.477) AM17(3.439,0.477) AM19(2.888,0.477) AM21(2.338,0.477) AM23(1.788,0.477) AM25(1.238,0.477) AM27(0.688,0.477) AM29(0.137,0.477) AM32(-0.413,0.477) AM34(-0.963,0.477) AM36(-1.513,0.477) AM38(-2.063,0.477) AM40(-2.614,0.477) AM42(-3.164,0.477) AM44(-3.714,0.477) AM46(-4.264,0.477) AP14(4.264,0.953) AP16(3.714,0.953) AP18(3.164,0.953) AP20(2.613,0.953) AP22(2.063,0.953) AP24(1.513,0.953) AP26(0.963,0.953) AP28(0.412,0.953) AP31(-0.138,0.953) AP33(-0.688,0.953) AP35(-1.238,0.953) AP37(-1.788,0.953) AP39(-2.339,0.953) AP41(-2.889,0.953) AP43(-3.439,0.953) AP45(-3.989,0.953) AT15(3.989,1.43) AT17(3.439,1.43) AT19(2.888,1.43) AT21(2.338,1.43) AT23(1.788,1.43) AT25(1.238,1.43) AT27(0.688,1.43) AT29(0.137,1.43) AT32(-0.413,1.43) AT34(-0.963,1.43) AT36(-1.513,1.43) AT38(-2.063,1.43) AT40(-2.614,1.43) AT42(-3.164,1.43) AT44(-3.714,1.43) AT46(-4.264,1.43) AU14(4.264,1.906) AU16(3.714,1.906) AU18(3.164,1.906) AU20(2.613,1.906) AU22(2.063,1.906) AU24(1.513,1.906) AU26(0.963,1.906) AU28(0.412,1.906) AU31(-0.138,1.906) AU33(-0.688,1.906) AU35(-1.238,1.906) AU37(-1.788,1.906) AU39(-2.339,1.906) AU41(-2.889,1.906) AU43(-3.439,1.906) AU45(-3.989,1.906) AW15(3.989,2.383) AW17(3.439,2.383) AW19(2.888,2.383) AW21(2.338,2.383) AW23(1.788,2.383) AW25(1.238,2.383) AW27(0.688,2.383) AW29(0.137,2.383) AW32(-0.413,2.383) AW34(-0.963,2.383) AW36(-1.513,2.383) AW38(-2.063,2.383) AW40(-2.614,2.383) AW42(-3.164,2.383) AW44(-3.714,2.383) AW46(-4.264,2.383) BA14(4.264,2.859) BA16(3.714,2.859) BA18(3.164,2.859) BA20(2.613,2.859) BA22(2.063,2.859) BA24(1.513,2.859) BA26(0.963,2.859) BA28(0.412,2.859) BA31(-0.138,2.859) BA33(-0.688,2.859) BA35(-1.238,2.859) BA37(-1.788,2.859) BA39(-2.339,2.859) BA41(-2.889,2.859) BA43(-3.439,2.859) BA45(-3.989,2.859) BB15(3.989,3.336) BB17(3.439,3.336) BB19(2.888,3.336) BB21(2.338,3.336) BB23(1.788,3.336) BB25(1.238,3.336) BB27(0.688,3.336) BB29(0.137,3.336) BB32(-0.413,3.336) BB34(-0.963,3.336) BB36(-1.513,3.336) BB38(-2.063,3.336) BB40(-2.614,3.336) BB42(-3.164,3.336) BB44(-3.714,3.336) BB46(-4.264,3.336) BD14(4.264,3.812) BD16(3.714,3.812) BD18(3.164,3.812) BD20(2.613,3.812) BD22(2.063,3.812) BD24(1.513,3.812) BD26(0.963,3.812) BD28(0.412,3.812) BD31(-0.138,3.812) BD33(-0.688,3.812) BD35(-1.238,3.812) BD37(-1.788,3.812) BD39(-2.339,3.812) BD41(-2.889,3.812) BD43(-3.439,3.812) BD45(-3.989,3.812) BF15(3.989,4.289) BF17(3.439,4.289) BF19(2.888,4.289) BF21(2.338,4.289) BF23(1.788,4.289) BF25(1.238,4.289) BF27(0.688,4.289) BF29(0.137,4.289) BF32(-0.413,4.289) BF34(-0.963,4.289) BF36(-1.513,4.289) BF38(-2.063,4.289) BF40(-2.614,4.289) BF42(-3.164,4.289) BF44(-3.714,4.289) BF46(-4.264,4.289) P15(3.989,-4.289) P17(3.439,-4.289) P19(2.888,-4.289) P21(2.338,-4.289) P23(1.788,-4.289) P25(1.238,-4.289) P27(0.688,-4.289) P29(0.137,-4.289) P32(-0.413,-4.289) P34(-0.963,-4.289) P36(-1.513,-4.289) P38(-2.063,-4.289) P40(-2.614,-4.289) P42(-3.164,-4.289) P44(-3.714,-4.289) P46(-4.264,-4.289) T14(4.264,-3.812) T16(3.714,-3.812) T18(3.164,-3.812) T20(2.613,-3.812) T22(2.063,-3.812) T24(1.513,-3.812) T26(0.963,-3.812) T28(0.412,-3.812) T31(-0.138,-3.812) T33(-0.688,-3.812) T35(-1.238,-3.812) T37(-1.788,-3.812) T39(-2.339,-3.812) T41(-2.889,-3.812) T43(-3.439,-3.812) T45(-3.989,-3.812) V15(3.989,-3.336) V17(3.439,-3.336) V19(2.888,-3.336) V21(2.338,-3.336) V23(1.788,-3.336) V25(1.238,-3.336) V27(0.688,-3.336) V29(0.137,-3.336) V32(-0.413,-3.336) V34(-0.963,-3.336) V36(-1.513,-3.336) V38(-2.063,-3.336) V40(-2.614,-3.336) V42(-3.164,-3.336) V44(-3.714,-3.336) V46(-4.264,-3.336) W14(4.264,-2.859) W16(3.714,-2.859) W18(3.164,-2.859) W20(2.613,-2.859) W22(2.063,-2.859) W24(1.513,-2.859) W26(0.963,-2.859) W28(0.412,-2.859) W31(-0.138,-2.859) W33(-0.688,-2.859) W35(-1.238,-2.859) W37(-1.788,-2.859) W39(-2.339,-2.859) W41(-2.889,-2.859) W43(-3.439,-2.859) W45(-3.989,-2.859)
